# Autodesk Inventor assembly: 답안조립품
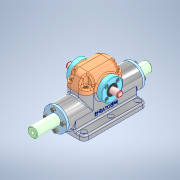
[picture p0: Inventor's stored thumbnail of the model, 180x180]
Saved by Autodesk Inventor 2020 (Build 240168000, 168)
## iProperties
Created: 2024-06
Part Number: 답안조립품
Document SubType Name: Assembly
Designer: oem
Author: oem
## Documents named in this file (13)
- C:\Users\oem\Desktop\740604V1015\답안조립품.iam
- C:\Users\oem\Desktop\740604V1015\본체.ipt
- C:\Users\oem\Desktop\740604V1015\오일레스 부시.ipt
- C:\Users\oem\Desktop\740604V1015\부시 커버.ipt
- C:\Users\oem\Desktop\740604V1015\스프링 와셔 M4.ipt
- C:\Users\oem\Desktop\740604V1015\육각 소켓 머리 볼트 M4x10.ipt
- C:\Users\oem\Desktop\740604V1015\랙.ipt
- C:\Users\oem\Desktop\740604V1015\깊은 홈 볼 베어링 6901.ipt
- C:\Users\oem\Desktop\740604V1015\칼라.ipt
- C:\Users\oem\Desktop\740604V1015\피니언.ipt
- C:\Users\oem\Desktop\740604V1015\윗커버.ipt
- C:\Users\oem\Desktop\740604V1015\베어링 커버.ipt
- C:\Users\oem\Desktop\740604V1015\오일실 12 22 7.ipt
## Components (1 placed, 1 different names)
1. 피니언:1
